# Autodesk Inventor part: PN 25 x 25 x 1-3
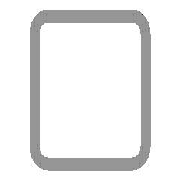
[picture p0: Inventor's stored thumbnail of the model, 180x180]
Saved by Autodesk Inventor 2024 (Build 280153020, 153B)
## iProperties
IsCustomPart: 1
Company: ATC
Created: 2023-03
Part Number: PN 25 x 25 x 1-3
Material: Stal, miękka
Description: Rury stalowe do zastosowań precyzyjnych -  (Część 5: Rury kwadratowe, spawane, wymiarowane na zimno)
Document SubType Name: Modeling
Standard: PN
Designer: Andrzej Jaskulski
Standards Organization: PN
Language: pl-PL
Size Designation: 25 x 25 x 1
Categories: <MemberInstance><Categories><Category DisplayName="Kształtowniki konstrukcyjne" InternalName="089c4875-fa83-4c05-b084-43b9cc11f5ed" Mnemonic="GRDR"><CategoryPar
Density: 7.85 g/cm^3
Appearance: Częściowo polerowany
Checked By: A.J.
Engr Approved By: Andrzej Jaskulski
Mfg Approved By: Andrzej Jaskulski
Authority: A.J.
Stock Number: 25 x 25 x 1
G_L: 541,619 mm
G_W: 25,000 mm
G_H: 25,000 mm
+D823DF31-F982-4AB8-9224-3942E330837F+CUTDETAIL1: Połączenie narożnikowe 40,39 deg
+4D2D2CB4-5467-4B56-8263-7C69A3E0AAF8+CUTDETAIL2: Połączenie narożnikowe 24,91 deg
_CCFamilyMember: 9
_CCFamilyDisplayName: PN EN 10305-5 (Rury kwadratowe, spawane, wymiarowane na zimno) - Rury stalowe do zastosowań precyzyjnych -  (Część 5: Rury kwadratowe, spawane, wymiarowane na z
_FrameMemberDoc: Frame Member File
_Version: 25.0.0
_GetPNFromCC: 0
Author: Andrzej Jaskulski
Revision Number: 1/24
Title: A.J.: Kurs R2024-MEP
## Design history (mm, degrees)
node "Płaszczyzna początkowa"
node "Płaszczyzna końcowa"
sketch "Szkic"
  geometry: L1 (-12.5, -11)-(-12.5, 11); L2 (-11, 12.5)-(11, 12.5); L3 (12.5, 11)-(12.5, -11); L4 (11, -12.5)-(-11, -12.5); L5 (-11, 11.5)-(11, 11.5); L6 (11.5, 11)-(11.5, -11); L7 (11, -11.5)-(-11, -11.5); L8 (-11.5, -11)-(-11.5, 11); L9 (0, 18.044)-(0, -18.044) reference; L10 (-18.044, 0)-(18.044, 0) reference; A1 r 1.5 centre (-11, -11) between (-12.5, -11) and (-11, -12.5); A2 r 1.5 centre (-11, 11) between (-11, 12.5) and (-12.5, 11); A3 r 1.5 centre (11, 11) between (12.5, 11) and (11, 12.5); A4 r 1.5 centre (11, -11) between (11, -12.5) and (12.5, -11); A5 r 0.5 centre (-11, 11) between (-11, 11.5) and (-11.5, 11); A6 r 0.5 centre (11, 11) between (11.5, 11) and (11, 11.5); A7 r 0.5 centre (11, -11) between (11, -11.5) and (11.5, -11); A8 r 0.5 centre (-11, -11) between (-11.5, -11) and (-11, -11.5)
  constraints: 16 end point, 16 point on circle, 8 centre point, 8 tangent, 4 parallel, 3 equal radius, 2 perpendicular, 7 other
  dimensions: "d7" = 1.5 radius of A1 (= G_IR); "d10" = 25 distance between parallel lines of L2 L4 (= G_H); "d11" = 25 distance between parallel lines of L1 L3 (= G_W); "d12" = 1 distance between parallel lines of L3 L6 (= G_T); "d15" = 12.5 distance between parallel lines of L2 L10 (= 0.5 x d10); "d16" = 12.5 distance between parallel lines of L9 L3 (= 0.5 x d11)
extrude "Bryła" new body sketch "Szkic" stored distance "d3" = 541.61852 (= G_L); taper "d4" = 0 deg
node "Driven Length"
  sketch "Sketch3"
    geometry: L1 (0, 0)-(10, 0) reference
    constraints: 2 end point, 1 horizontal
  workplane "Work Plane3"
node "Płaszczyzna konstrukcyjna4"
feature "Podział1"
node "Płaszczyzna konstrukcyjna5"
feature "Podział2"
body "Solid1"
sketch "Sketch4"
  geometry: L1 (-2, -26.921)-(12, -26.921) reference; L2 (-2, 514.697)-(12, 514.697) reference
  dimensions: "d18" = 541.61852 distance between parallel lines of L1 L2 (derived)
other parameters: "G_W" = 25 [user parameter; used in 1 equation term], "G_H" = 25 [user parameter; used in 1 equation term], "G_T" = 1 [user parameter; used in 1 equation term], "G_IR" = 1.5 [user parameter; used in 1 equation term], "G_L" = 541.61852 (= d18) [user parameter; used in 1 equation term], "G_OFFSET_START" = 26.92139 [user parameter; used in 1 equation term], "G_OFFSET_END" = 14.69144 [user parameter; used in 1 equation term], "d13" = -26.92139 (= -G_OFFSET_START), "d14" = 514.69712 (= G_OFFSET_END + B_L), "B_L" = 500.00569 [user parameter; used in 1 equation term], "d17" = 90 deg
